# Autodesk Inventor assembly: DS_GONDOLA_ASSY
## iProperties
Shininess: 64.0
Length Units: 11272
Angle Units: 11279
Time Units: 11290
Mass Units: 11286
Length Display Precision: 3
Angle Display Precision: 2
Compacted: True
Part Number: DS_GONDOLA_ASSY
Document SubType Name: Assembly
Created: 2004-08
Designer: John Blackburn
Manufacturer: Standard
Standards Organization: Custom
Density: 0.0
Volumn: 0.0
Area: 0.0
PropertySet Name: Model Information
Control State: 0
Master: False
Checked Out: False
Author: John Blackburn
